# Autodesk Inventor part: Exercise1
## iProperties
Shininess: 77.0
Length Units: 11269
Angle Units: 11279
Time Units: 11290
Mass Units: 11283
Length Display Precision: 3
Angle Display Precision: 2
Created: 2001-12
Part Number: Exercise1
Document SubType Name: Modeling
Designer: Renu Muthoo
Density: 1 g/cm^3
Density: 0.0
Volumn: 0.0
Area: 0.0
PropertySet Name: Model Information
Control State: 0
Master: False
Checked Out: False
Author: Renu Muthoo
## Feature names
1. Extrusion1
2. Extrusion2
3. Hole1
4. Fillet1
